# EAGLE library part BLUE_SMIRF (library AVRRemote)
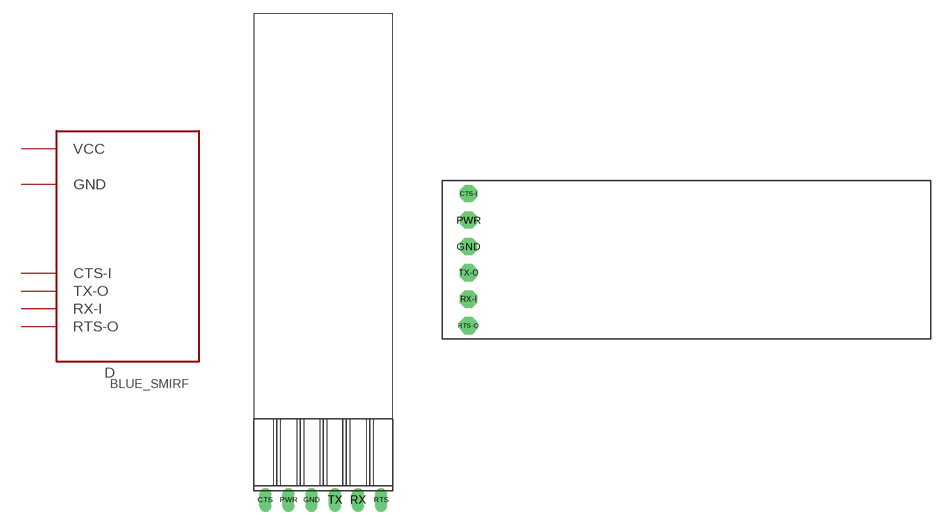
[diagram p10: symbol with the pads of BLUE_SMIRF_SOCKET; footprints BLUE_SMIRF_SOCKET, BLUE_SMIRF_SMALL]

Designator prefix D

## BLUE_SMIRF  [BLUE_SMIRF_SOCKET]
CTS  CTS-I  in
GND  GND  sup
PWR  VCC  sup
RTS  RTS-O  out
RX  RX-I  in
TX  TX-O  out

## BLUE_SMIRFSMALL  [BLUE_SMIRF_SMALL]
CTS-I  CTS-I  in
GND  GND  sup
PWR  VCC  sup
RTS-O  RTS-O  out
RX-I  RX-I  in
TX-O  TX-O  out

## Footprint BLUE_SMIRF_SOCKET (pad centres in mm)
drill 0.813 long: CTS -6.35,-8.89; GND -1.27,-8.89; PWR -3.81,-8.89; RTS 6.35,-8.89; RX 3.81,-8.89; TX 1.27,-8.89

## Footprint BLUE_SMIRF_SMALL (pad centres in mm)
drill 1.1 octagon: CTS-I 0,6.35; GND 0,1.27; PWR 0,3.81; RTS-O 0,-6.35; RX-I 0,-3.81; TX-O 0,-1.27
